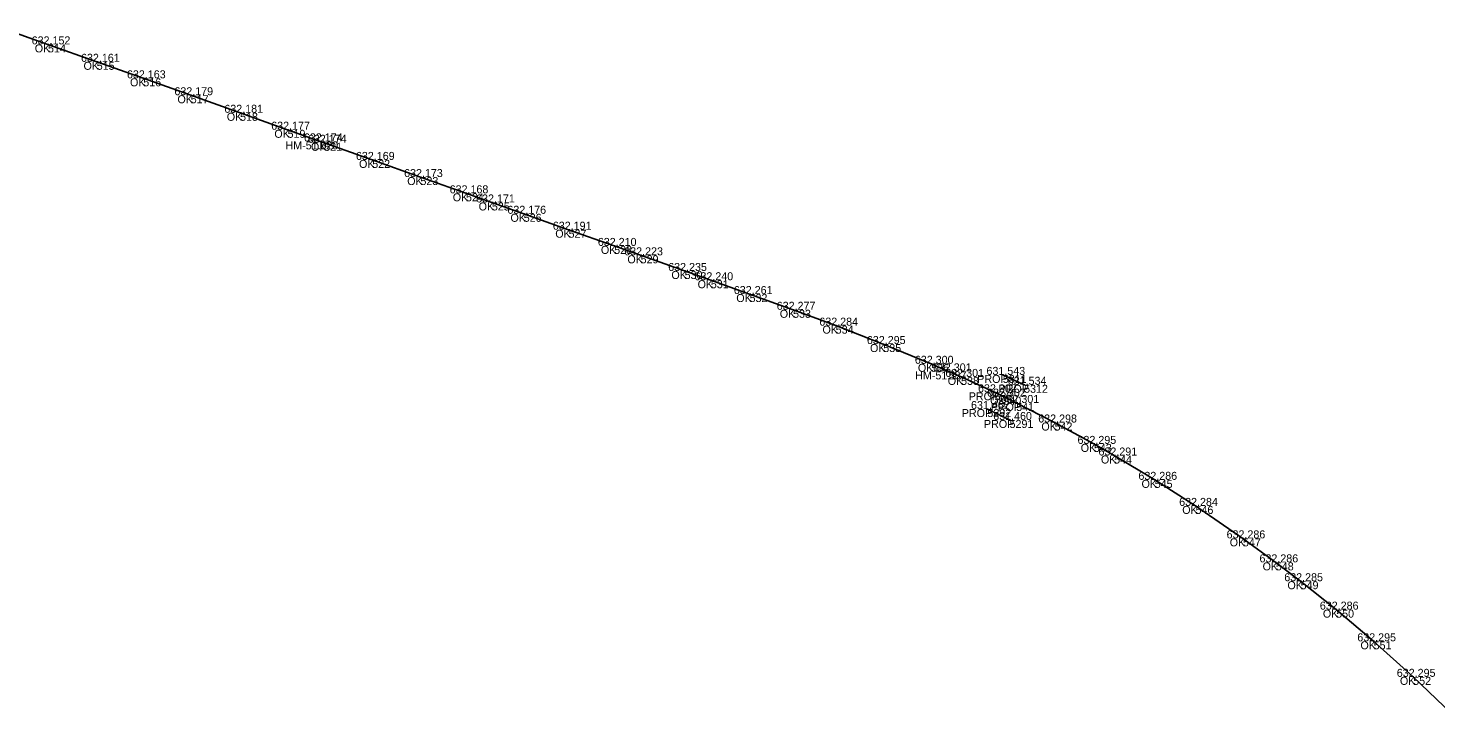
# Model space of a CAD drawing. Extents: x -631472 to -620808, y -1122356 to -1115125.
# Drawn here: x -628519.1 to -628308, y -1116473.9 to -1116371 of the extents above; entities that cross this region are included whole.
import ezdxf

# ---------------------------------------------------------------- set-up
doc = ezdxf.new("R2010")
doc.units = 0
for name, color, linetype in [('Vrstva 1', 7, 'Continuous'), ('Vrstva 18', 7, 'Continuous'), ('Vrstva 60', 7, 'Continuous'), ('Vrstva 61', 7, 'Continuous'), ('Vrstva 62', 7, 'Continuous')]:
    doc.layers.add(name, color=color, linetype=linetype)

msp = doc.modelspace()

# ---------------------------------------------------------------- linework, layer by layer
at = {"layer": 'Vrstva 1'}
msp.add_lwpolyline([(-628522.94, -1116371.04), (-628516.08, -1116373.48), (-628508.77, -1116376.09), (-628501.79, -1116378.57), (-628494.68, -1116381.11), (-628487.28, -1116383.74), (-628480.16, -1116386.28), (-628475.26, -1116388.03), (-628474.66, -1116388.24), (-628467.46, -1116390.81), (-628460.24, -1116393.38), (-628453.41, -1116395.82), (-628449.53, -1116397.19), (-628444.75, -1116398.89), (-628438.03, -1116401.28), (-628431.19, -1116403.71), (-628427.22, -1116405.12), (-628420.63, -1116407.47), (-628416.7, -1116408.86), (-628410.89, -1116410.93), (-628404.37, -1116413.29), (-628397.98, -1116415.67), (-628390.84, -1116418.43), (-628383.66, -1116421.39), (-628381.05, -1116422.53), (-628379.18, -1116423.36), (-628374.19, -1116425.67), (-628372.83, -1116426.32), (-628370.91, -1116427.27), (-628365.16, -1116430.2), (-628359.26, -1116433.41), (-628356.23, -1116435.15), (-628350.14, -1116438.8), (-628344.03, -1116442.71), (-628336.92, -1116447.58), (-628331.99, -1116451.18), (-628328.27, -1116454.01), (-628322.94, -1116458.27), (-628317.32, -1116463.02), (-628311.39, -1116468.35), (-628305.6, -1116473.9)], dxfattribs=at)
at = {"layer": 'Vrstva 18'}
for p, q in [((-628372.92, -1116423.06), (-628369.73, -1116424.54)), ((-628375.24, -1116428.18), (-628371.91, -1116429.82))]:
    msp.add_line(p, q, dxfattribs=at)
at = {"layer": 'Vrstva 60'}
for p, q in [((-628516.08, -1116373.48), (-628516.08, -1116373.48)), ((-628508.77, -1116376.09), (-628508.77, -1116376.09)), ((-628501.79, -1116378.57), (-628501.79, -1116378.57)), ((-628494.68, -1116381.11), (-628494.68, -1116381.11)), ((-628487.28, -1116383.74), (-628487.28, -1116383.74)), ((-628480.16, -1116386.28), (-628480.16, -1116386.28)), ((-628475.26, -1116388.03), (-628475.26, -1116388.03)), ((-628474.66, -1116388.24), (-628474.66, -1116388.24)), ((-628467.46, -1116390.81), (-628467.46, -1116390.81)), ((-628460.24, -1116393.38), (-628460.24, -1116393.38)), ((-628453.41, -1116395.82), (-628453.41, -1116395.82)), ((-628449.53, -1116397.19), (-628449.53, -1116397.19)), ((-628444.75, -1116398.89), (-628444.75, -1116398.89)), ((-628438.03, -1116401.28), (-628438.03, -1116401.28)), ((-628431.19, -1116403.71), (-628431.19, -1116403.71)), ((-628427.22, -1116405.12), (-628427.22, -1116405.12)), ((-628420.63, -1116407.47), (-628420.63, -1116407.47)), ((-628416.7, -1116408.86), (-628416.7, -1116408.86)), ((-628410.89, -1116410.93), (-628410.89, -1116410.93)), ((-628404.37, -1116413.29), (-628404.37, -1116413.29)), ((-628397.98, -1116415.67), (-628397.98, -1116415.67)), ((-628390.84, -1116418.43), (-628390.84, -1116418.43)), ((-628383.66, -1116421.39), (-628383.66, -1116421.39)), ((-628381.05, -1116422.53), (-628381.05, -1116422.53)), ((-628379.18, -1116423.36), (-628379.18, -1116423.36)), ((-628374.19, -1116425.67), (-628374.19, -1116425.67)), ((-628372.83, -1116426.32), (-628372.83, -1116426.32)), ((-628370.91, -1116427.27), (-628370.91, -1116427.27)), ((-628365.16, -1116430.2), (-628365.16, -1116430.2)), ((-628359.26, -1116433.41), (-628359.26, -1116433.41)), ((-628356.23, -1116435.15), (-628356.23, -1116435.15)), ((-628350.14, -1116438.8), (-628350.14, -1116438.8)), ((-628344.03, -1116442.71), (-628344.03, -1116442.71)), ((-628336.92, -1116447.58), (-628336.92, -1116447.58)), ((-628331.99, -1116451.18), (-628331.99, -1116451.18)), ((-628328.27, -1116454.01), (-628328.27, -1116454.01)), ((-628322.94, -1116458.27), (-628322.94, -1116458.27)), ((-628317.32, -1116463.02), (-628317.32, -1116463.02)), ((-628311.39, -1116468.35), (-628311.39, -1116468.35))]:
    msp.add_line(p, q, dxfattribs=at)

# ---------------------------------------------------------------- texts
for s, p in [('514', (-628516.08, -1116374.68)), ('515', (-628508.77, -1116377.29)), ('516', (-628501.79, -1116379.77)), ('517', (-628494.68, -1116382.31)), ('518', (-628487.28, -1116384.94)), ('519', (-628480.16, -1116387.49)), ('520', (-628475.26, -1116389.23)), ('521', (-628474.66, -1116389.44)), ('522', (-628467.46, -1116392.01)), ('523', (-628460.24, -1116394.58)), ('524', (-628453.41, -1116397.02)), ('525', (-628449.53, -1116398.39)), ('526', (-628444.75, -1116400.09)), ('527', (-628438.03, -1116402.48)), ('528', (-628431.19, -1116404.91)), ('529', (-628427.22, -1116406.32)), ('530', (-628420.63, -1116408.67)), ('531', (-628416.7, -1116410.06)), ('532', (-628410.89, -1116412.13)), ('533', (-628404.37, -1116414.49)), ('534', (-628397.98, -1116416.87)), ('535', (-628390.84, -1116419.63)), ('536', (-628383.66, -1116422.59)), ('537', (-628381.05, -1116423.73)), ('538', (-628379.18, -1116424.56)), ('5311', (-628372.92, -1116424.26)), ('539', (-628374.19, -1116426.87)), ('540', (-628372.83, -1116427.52)), ('5312', (-628369.73, -1116425.74)), ('5292', (-628375.24, -1116429.38)), ('541', (-628370.91, -1116428.47)), ('5291', (-628371.91, -1116431.02)), ('542', (-628365.16, -1116431.4)), ('543', (-628359.26, -1116434.61)), ('544', (-628356.23, -1116436.35)), ('545', (-628350.14, -1116440)), ('546', (-628344.03, -1116443.91)), ('547', (-628336.92, -1116448.78)), ('548', (-628331.99, -1116452.38)), ('549', (-628328.27, -1116455.21)), ('550', (-628322.94, -1116459.47)), ('551', (-628317.32, -1116464.22)), ('552', (-628311.39, -1116469.55))]:
    msp.add_text(s, height=1.2, dxfattribs=at).set_placement(p)
at = {"layer": 'Vrstva 61'}
for s, p in [('632.152', (-628518.53, -1116373.48)), ('632.161', (-628511.13, -1116376.09)), ('632.163', (-628504.24, -1116378.57)), ('632.179', (-628497.13, -1116381.11)), ('632.181', (-628489.64, -1116383.74)), ('632.177', (-628482.61, -1116386.28)), ('632.174', (-628477.71, -1116388.03)), ('632.174', (-628477.11, -1116388.24)), ('632.169', (-628469.91, -1116390.81)), ('632.173', (-628462.69, -1116393.38)), ('632.168', (-628455.86, -1116395.82)), ('632.171', (-628451.89, -1116397.19)), ('632.176', (-628447.2, -1116398.89)), ('632.191', (-628440.39, -1116401.28)), ('632.210', (-628433.64, -1116403.71)), ('632.223', (-628429.68, -1116405.12)), ('632.235', (-628423.09, -1116407.47)), ('632.240', (-628419.15, -1116408.86)), ('632.261', (-628413.25, -1116410.93)), ('632.277', (-628406.82, -1116413.29)), ('632.284', (-628400.43, -1116415.67)), ('632.295', (-628393.3, -1116418.43)), ('632.300', (-628386.11, -1116421.39)), ('632.301', (-628383.4, -1116422.53)), ('632.301', (-628381.54, -1116423.36)), ('631.543', (-628375.37, -1116423.06)), ('631.534', (-628372.18, -1116424.54)), ('632.302', (-628376.64, -1116425.67)), ('632.302', (-628375.28, -1116426.32)), ('632.301', (-628373.26, -1116427.27)), ('631.462', (-628377.69, -1116428.18)), ('631.460', (-628374.36, -1116429.82)), ('632.298', (-628367.61, -1116430.2)), ('632.295', (-628361.72, -1116433.41)), ('632.291', (-628358.58, -1116435.15)), ('632.286', (-628352.59, -1116438.8)), ('632.284', (-628346.48, -1116442.71)), ('632.286', (-628339.37, -1116447.58)), ('632.286', (-628334.44, -1116451.18)), ('632.285', (-628330.72, -1116454.01)), ('632.286', (-628325.39, -1116458.27)), ('632.295', (-628319.77, -1116463.02)), ('632.295', (-628313.85, -1116468.35))]:
    msp.add_text(s, height=1.2, dxfattribs=at).set_placement(p)
at = {"layer": 'Vrstva 62'}
for s, p in [('OK', (-628518.06, -1116374.68)), ('OK', (-628510.75, -1116377.29)), ('OK', (-628503.78, -1116379.77)), ('OK', (-628496.67, -1116382.31)), ('OK', (-628489.27, -1116384.94)), ('OK', (-628482.14, -1116387.49)), ('HM-51.0', (-628480.47, -1116389.23)), ('OK', (-628476.65, -1116389.44)), ('OK', (-628469.44, -1116392.01)), ('OK', (-628462.22, -1116394.58)), ('OK', (-628455.39, -1116397.02)), ('OK', (-628451.51, -1116398.39)), ('OK', (-628446.74, -1116400.09)), ('OK', (-628440.02, -1116402.48)), ('OK', (-628433.18, -1116404.91)), ('OK', (-628429.21, -1116406.32)), ('OK', (-628422.61, -1116408.67)), ('OK', (-628418.68, -1116410.06)), ('OK', (-628412.88, -1116412.13)), ('OK', (-628406.36, -1116414.49)), ('OK', (-628399.96, -1116416.87)), ('OK', (-628392.83, -1116419.63)), ('OK', (-628385.65, -1116422.59)), ('HM-51.1', (-628386.06, -1116423.73)), ('OK', (-628381.17, -1116424.56)), ('PROP', (-628376.75, -1116424.26)), ('PROP', (-628378.03, -1116426.87)), ('OK', (-628374.82, -1116427.52)), ('PROP', (-628373.56, -1116425.74)), ('PROP', (-628379.07, -1116429.38)), ('PROP', (-628374.74, -1116428.47)), ('PROP', (-628375.75, -1116431.02)), ('OK', (-628367.14, -1116431.4)), ('OK', (-628361.24, -1116434.61)), ('OK', (-628358.21, -1116436.35)), ('OK', (-628352.12, -1116440)), ('OK', (-628346.02, -1116443.91)), ('OK', (-628338.9, -1116448.78)), ('OK', (-628333.97, -1116452.38)), ('OK', (-628330.25, -1116455.21)), ('OK', (-628324.93, -1116459.47)), ('OK', (-628319.3, -1116464.22)), ('OK', (-628313.38, -1116469.55))]:
    msp.add_text(s, height=1.2, dxfattribs=at).set_placement(p)

doc.saveas('drawing.dxf')
